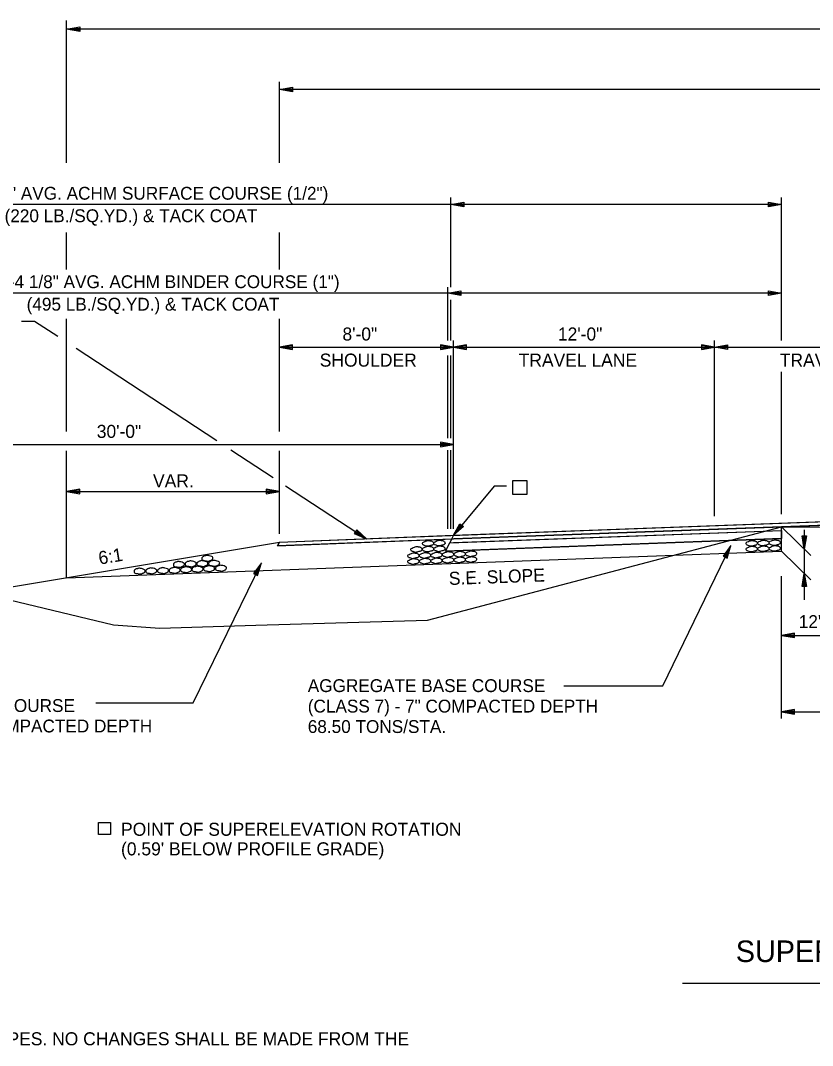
# Model space of a CAD drawing. Extents: x 1461846 to 1462006, y 1686171 to 1686805.
# Drawn here: x 1461877.78 to 1461914.18, y 1686329.7 to 1686376.8 of the extents above; entities that cross this region are included whole.
import ezdxf

# ---------------------------------------------------------------- set-up
doc = ezdxf.new("R2010")
doc.units = 0
for name, color, linetype in [('1', 7, 'Continuous'), ('10', 7, 'Continuous'), ('12', 7, 'Continuous'), ('19', 7, 'Continuous'), ('20', 7, 'Continuous'), ('3', 7, 'Continuous'), ('42', 7, 'Continuous'), ('R_Draft', 7, 'Continuous')]:
    doc.layers.add(name, color=color, linetype=linetype)

# ---------------------------------------------------------------- blocks, each defined once
blk = doc.blocks.new('ROCKS')
at = {"layer": '1'}
blk.add_spline([(0.013, 0.06), (0.053, 0.053), (0.107, 0.033), (0.133, 0.013), (0.133, -0.007), (0.12, -0.033), (0.107, -0.04), (0.073, -0.053), (0.033, -0.067), (0.013, -0.067), (-0.02, -0.06), (-0.06, -0.053), (-0.087, -0.047), (-0.113, -0.02), (-0.113, -0.007), (-0.107, 0.02), (-0.087, 0.033), (-0.067, 0.047), (-0.033, 0.053), (-0.02, 0.06), (0.013, 0.06)], degree=3, dxfattribs=at)

msp = doc.modelspace()

# ---------------------------------------------------------------- linework, layer by layer
at = {"layer": '10'}
msp.add_lwpolyline([(1461901.048, 1686355.021), (1461900.407, 1686355.021), (1461900.407, 1686355.662), (1461901.048, 1686355.662), (1461901.048, 1686355.021)], dxfattribs=at)
at = {"layer": '19'}
for p, q in [((1461912.763, 1686353.368), (1461912.763, 1686353.368)), ((1461897.68, 1686353.143), (1461897.318, 1686352.42)), ((1461913.703, 1686353.112), (1461913.913, 1686353.112)), ((1461913.808, 1686352.512), (1461913.703, 1686353.112)), ((1461913.793, 1686352.672), (1461913.753, 1686353.112)), ((1461913.913, 1686353.112), (1461913.808, 1686352.512)), ((1461913.858, 1686353.112), (1461913.823, 1686352.672)), ((1461889.68, 1686352.823), (1461889.595, 1686352.653)), ((1461897.318, 1686352.42), (1461897.51, 1686352.803)), ((1461897.51, 1686352.803), (1461897.51, 1686352.803)), ((1461907.301, 1686346.235), (1461910.435, 1686352.674)), ((1461910.435, 1686352.674), (1461910.071, 1686352.185)), ((1461910.353, 1686352.537), (1461910.12, 1686352.164)), ((1461910.214, 1686352.115), (1461910.378, 1686352.524)), ((1461910.258, 1686352.093), (1461910.435, 1686352.674)), ((1461897.318, 1686352.42), (1461897.318, 1686352.42)), ((1461910.071, 1686352.185), (1461910.258, 1686352.093)), ((1461885.72, 1686345.442), (1461888.854, 1686351.881)), ((1461888.854, 1686351.881), (1461888.49, 1686351.392)), ((1461888.772, 1686351.744), (1461888.539, 1686351.371)), ((1461888.633, 1686351.322), (1461888.797, 1686351.731)), ((1461888.677, 1686351.299), (1461888.854, 1686351.881)), ((1461888.49, 1686351.392), (1461888.677, 1686351.299)), ((1461913.703, 1686350.787), (1461913.808, 1686351.387)), ((1461913.758, 1686350.787), (1461913.793, 1686351.227)), ((1461913.808, 1686351.387), (1461913.913, 1686350.787)), ((1461913.823, 1686351.227), (1461913.863, 1686350.787)), ((1461913.913, 1686350.787), (1461913.703, 1686350.787)), ((1461902.757, 1686346.235), (1461907.301, 1686346.235)), ((1461881.246, 1686345.442), (1461885.72, 1686345.442))]:
    msp.add_line(p, q, dxfattribs=at)
for points in [[(1461964.762, 1686355.458), (1461960.956, 1686355.318), (1461940.777, 1686354.571), (1461921.639, 1686353.863), (1461914.019, 1686353.581), (1461903.26, 1686353.183), (1461897.595, 1686352.973), (1461895.595, 1686352.893), (1461889.595, 1686352.653), (1461889.595, 1686352.653), (1461889.595, 1686352.653), (1461889.68, 1686352.823), (1461889.68, 1686352.823), (1461889.68, 1686352.823), (1461895.545, 1686353.058), (1461903.665, 1686353.365), (1461913.994, 1686353.747), (1461921.643, 1686354.03), (1461940.732, 1686354.736), (1461960.903, 1686355.482), (1461964.68, 1686355.622)], [(1461897.51, 1686352.803), (1461897.68, 1686352.81), (1461912.763, 1686353.368), (1461912.763, 1686353.368), (1461912.763, 1686353.368), (1461912.763, 1686353.534), (1461912.763, 1686353.534), (1461912.763, 1686353.534), (1461897.7, 1686352.977), (1461897.595, 1686352.973)]]:
    msp.add_lwpolyline(points, close=True, dxfattribs=at)
for points in [[(1461912.763, 1686353.368), (1461912.763, 1686352.993), (1461897.318, 1686352.42), (1461897.318, 1686352.42), (1461897.318, 1686352.42)], [(1461897.51, 1686352.803), (1461897.51, 1686352.803), (1461897.51, 1686352.803), (1461912.763, 1686353.368)]]:
    msp.add_lwpolyline(points, dxfattribs=at)
at = {"layer": '20'}
for p, q in [((1461879.904, 1686370.26), (1461879.904, 1686376.797)), ((1461879.904, 1686376.393), (1461880.504, 1686376.499)), ((1461880.064, 1686376.408), (1461880.504, 1686376.444)), ((1461880.504, 1686376.499), (1461880.504, 1686376.289)), ((1461976.425, 1686376.393), (1461879.904, 1686376.393)), ((1461880.504, 1686376.289), (1461879.904, 1686376.393)), ((1461880.504, 1686376.339), (1461880.064, 1686376.378)), ((1461889.68, 1686370.26), (1461889.68, 1686373.976)), ((1461889.68, 1686373.624), (1461890.28, 1686373.729)), ((1461964.68, 1686373.624), (1461889.68, 1686373.624)), ((1461890.28, 1686373.519), (1461889.68, 1686373.624)), ((1461889.84, 1686373.639), (1461890.28, 1686373.674)), ((1461890.28, 1686373.729), (1461890.28, 1686373.519)), ((1461890.28, 1686373.569), (1461889.84, 1686373.609)), ((1461897.555, 1686364.538), (1461897.555, 1686368.657)), ((1461897.555, 1686368.339), (1461898.155, 1686368.444)), ((1461898.155, 1686368.444), (1461898.155, 1686368.234)), ((1461912.163, 1686368.234), (1461912.163, 1686368.444)), ((1461912.163, 1686368.444), (1461912.763, 1686368.339)), ((1461912.763, 1686362.092), (1461912.763, 1686368.657)), ((1461897.555, 1686368.339), (1461873.688, 1686368.339)), ((1461912.763, 1686368.339), (1461897.555, 1686368.339)), ((1461898.155, 1686368.234), (1461897.555, 1686368.339)), ((1461897.715, 1686368.354), (1461898.155, 1686368.389)), ((1461898.155, 1686368.284), (1461897.715, 1686368.324)), ((1461912.163, 1686368.389), (1461912.603, 1686368.354)), ((1461912.763, 1686368.339), (1461912.163, 1686368.234)), ((1461912.603, 1686368.324), (1461912.163, 1686368.284)), ((1461879.904, 1686365.357), (1461879.904, 1686367.061)), ((1461889.68, 1686365.357), (1461889.68, 1686367.061)), ((1461897.419, 1686364.27), (1461875.488, 1686364.27)), ((1461897.418, 1686364.27), (1461898.018, 1686364.375)), ((1461898.018, 1686364.165), (1461897.418, 1686364.27)), ((1461897.419, 1686362.092), (1461897.419, 1686364.538)), ((1461912.763, 1686364.272), (1461897.419, 1686364.272)), ((1461897.578, 1686364.285), (1461898.018, 1686364.32)), ((1461898.018, 1686364.215), (1461897.578, 1686364.255)), ((1461898.018, 1686364.375), (1461898.018, 1686364.165)), ((1461912.163, 1686364.167), (1461912.163, 1686364.377)), ((1461912.163, 1686364.377), (1461912.763, 1686364.272)), ((1461912.163, 1686364.322), (1461912.603, 1686364.287)), ((1461912.763, 1686364.272), (1461912.163, 1686364.167)), ((1461912.603, 1686364.257), (1461912.163, 1686364.217)), ((1461897.555, 1686362.092), (1461897.555, 1686363.96)), ((1461879.904, 1686357.918), (1461879.904, 1686363.084)), ((1461889.68, 1686362.092), (1461889.68, 1686363.084)), ((1461897.419, 1686357.605), (1461897.419, 1686361.398)), ((1461897.555, 1686357.605), (1461897.555, 1686361.398)), ((1461912.763, 1686354.12), (1461912.763, 1686360.658)), ((1461879.904, 1686351.194), (1461879.904, 1686357.018)), ((1461897.419, 1686353.443), (1461897.419, 1686357.062)), ((1461897.555, 1686353.443), (1461897.555, 1686357.062)), ((1461880.504, 1686355.266), (1461879.904, 1686355.161)), ((1461880.504, 1686355.056), (1461880.504, 1686355.266)), ((1461889.08, 1686355.266), (1461889.08, 1686355.056)), ((1461889.68, 1686355.161), (1461889.08, 1686355.266)), ((1461879.904, 1686355.161), (1461889.68, 1686355.161)), ((1461879.904, 1686355.161), (1461880.504, 1686355.056)), ((1461880.504, 1686355.211), (1461880.064, 1686355.176)), ((1461880.064, 1686355.146), (1461880.504, 1686355.106)), ((1461889.52, 1686355.176), (1461889.08, 1686355.211)), ((1461889.08, 1686355.056), (1461889.68, 1686355.161)), ((1461889.08, 1686355.106), (1461889.52, 1686355.146)), ((1461912.763, 1686353.534), (1461914.107, 1686352.219)), ((1461912.763, 1686352.409), (1461914.107, 1686351.094))]:
    msp.add_line(p, q, dxfattribs=at)
msp.add_lwpolyline([(1461913.808, 1686353.388), (1461913.808, 1686350.178)], dxfattribs=at)
at = {"layer": '3'}
msp.add_line((1461946.153, 1686332.55), (1461908.207, 1686332.55), dxfattribs=at)
at = {"layer": 'R_Draft'}
for p, q in [((1461889.68, 1686357.918), (1461889.68, 1686362.092)), ((1461890.28, 1686361.897), (1461889.68, 1686361.792)), ((1461890.28, 1686361.687), (1461890.28, 1686361.897)), ((1461897.08, 1686361.897), (1461897.08, 1686361.687)), ((1461897.68, 1686361.792), (1461897.08, 1686361.897)), ((1461897.68, 1686357.012), (1461897.68, 1686362.092)), ((1461898.28, 1686361.897), (1461897.68, 1686361.792)), ((1461898.28, 1686361.687), (1461898.28, 1686361.897)), ((1461909.08, 1686361.897), (1461909.08, 1686361.687)), ((1461909.68, 1686361.792), (1461909.08, 1686361.897)), ((1461909.68, 1686354.023), (1461909.68, 1686362.092)), ((1461909.68, 1686361.792), (1461910.28, 1686361.897)), ((1461910.28, 1686361.897), (1461910.28, 1686361.687)), ((1461889.68, 1686361.792), (1461897.68, 1686361.792)), ((1461889.68, 1686361.792), (1461890.28, 1686361.687)), ((1461890.28, 1686361.842), (1461889.84, 1686361.807)), ((1461889.84, 1686361.777), (1461890.28, 1686361.737)), ((1461897.52, 1686361.807), (1461897.08, 1686361.842)), ((1461897.08, 1686361.687), (1461897.68, 1686361.792)), ((1461897.08, 1686361.737), (1461897.52, 1686361.777)), ((1461897.68, 1686361.792), (1461909.68, 1686361.792)), ((1461897.68, 1686361.792), (1461898.28, 1686361.687)), ((1461898.28, 1686361.842), (1461897.84, 1686361.807)), ((1461897.84, 1686361.777), (1461898.28, 1686361.737)), ((1461909.52, 1686361.807), (1461909.08, 1686361.842)), ((1461909.08, 1686361.687), (1461909.68, 1686361.792)), ((1461909.08, 1686361.737), (1461909.52, 1686361.777)), ((1461909.68, 1686361.792), (1461921.68, 1686361.792)), ((1461910.28, 1686361.687), (1461909.68, 1686361.792)), ((1461909.84, 1686361.807), (1461910.28, 1686361.842)), ((1461910.28, 1686361.737), (1461909.84, 1686361.777)), ((1461867.68, 1686357.318), (1461897.68, 1686357.318)), ((1461897.08, 1686357.423), (1461897.08, 1686357.213)), ((1461897.68, 1686357.318), (1461897.08, 1686357.423)), ((1461897.52, 1686357.333), (1461897.08, 1686357.368)), ((1461897.08, 1686357.213), (1461897.68, 1686357.318)), ((1461897.08, 1686357.263), (1461897.52, 1686357.303)), ((1461889.68, 1686353.207), (1461889.68, 1686357.018)), ((1461897.68, 1686353.443), (1461897.68, 1686357.012)), ((1461893.236, 1686353.4), (1461893.121, 1686353.224)), ((1461893.68, 1686352.983), (1461893.236, 1686353.4)), ((1461897.68, 1686353.143), (1461897.978, 1686353.674)), ((1461898.139, 1686353.542), (1461897.68, 1686353.143)), ((1461897.772, 1686353.273), (1461898.016, 1686353.636)), ((1461898.102, 1686353.568), (1461897.793, 1686353.258)), ((1461897.978, 1686353.674), (1461898.139, 1686353.542)), ((1461912.763, 1686352.409), (1461912.763, 1686353.534)), ((1461889.595, 1686352.653), (1461897.68, 1686352.976)), ((1461889.68, 1686352.823), (1461897.68, 1686353.143)), ((1461893.121, 1686353.224), (1461893.68, 1686352.983)), ((1461893.151, 1686353.27), (1461893.538, 1686353.058)), ((1461893.554, 1686353.083), (1461893.208, 1686353.358)), ((1461867.68, 1686349.156), (1461889.68, 1686352.823)), ((1461897.318, 1686352.42), (1461897.68, 1686352.435)), ((1461897.51, 1686352.803), (1461897.68, 1686352.81)), ((1461912.763, 1686344.731), (1461912.763, 1686351.268)), ((1461913.358, 1686348.652), (1461912.758, 1686348.547)), ((1461912.758, 1686348.547), (1461924.763, 1686348.547)), ((1461912.758, 1686348.547), (1461913.358, 1686348.442)), ((1461913.358, 1686348.597), (1461912.918, 1686348.562)), ((1461912.918, 1686348.532), (1461913.358, 1686348.492)), ((1461913.358, 1686348.442), (1461913.358, 1686348.652)), ((1461913.363, 1686345.138), (1461912.763, 1686345.033)), ((1461912.763, 1686345.033), (1461940.18, 1686345.033)), ((1461912.763, 1686345.033), (1461913.363, 1686344.928)), ((1461913.363, 1686345.083), (1461912.923, 1686345.048)), ((1461912.923, 1686345.018), (1461913.363, 1686344.978)), ((1461913.363, 1686344.928), (1461913.363, 1686345.138))]:
    msp.add_line(p, q, dxfattribs=at)
for points in [[(1461877.833, 1686362.988), (1461878.433, 1686362.988), (1461879.498, 1686362.289)], [(1461880.338, 1686361.737), (1461886.801, 1686357.497)], [(1461887.444, 1686357.075), (1461889.4, 1686355.792)], [(1461889.967, 1686355.419), (1461893.68, 1686352.983)], [(1461900.123, 1686355.407), (1461899.553, 1686355.407), (1461897.68, 1686353.143)], [(1461897.68, 1686353.143), (1461927.18, 1686354.235), (1461956.68, 1686355.326)], [(1461900.407, 1686355.021), (1461900.407, 1686355.662), (1461901.048, 1686355.662), (1461901.048, 1686355.021), (1461900.407, 1686355.021)], [(1461897.68, 1686352.976), (1461927.18, 1686354.068), (1461956.68, 1686355.159)], [(1461847.362, 1686353.269), (1461867.322, 1686352.565), (1461882.06, 1686349.033), (1461884.194, 1686348.879), (1461888.604, 1686349.011), (1461896.486, 1686349.242), (1461912.763, 1686353.534), (1461918.661, 1686353.486), (1461934.122, 1686354.079), (1461940.18, 1686354.549), (1461946.68, 1686353.887), (1461962.552, 1686349.481)], [(1461897.68, 1686352.976), (1461918.68, 1686353.753)], [(1461897.68, 1686352.81), (1461912.763, 1686353.368)], [(1461897.68, 1686352.435), (1461912.763, 1686352.993)], [(1461879.904, 1686351.194), (1461912.763, 1686352.409)], [(1461881.362, 1686339.396), (1461881.362, 1686339.956), (1461881.922, 1686339.956), (1461881.922, 1686339.396), (1461881.362, 1686339.396)]]:
    msp.add_lwpolyline(points, dxfattribs=at)

# ---------------------------------------------------------------- block references
at = {"layer": '19'}
for p, xscale, yscale, rotation in [((1461896.532, 1686352.781), 2.0611362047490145, -2.0611362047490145, -176.23624371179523), ((1461897.06, 1686352.796), 2.0611362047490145, -2.0611362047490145, -176.23624371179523), ((1461911.412, 1686352.783), 2.0611362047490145, -2.0611362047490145, -176.23624371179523), ((1461911.942, 1686352.799), 2.0611362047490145, -2.0611362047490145, -176.23624371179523), ((1461912.47, 1686352.814), 2.0611362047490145, -2.0611362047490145, -176.23624371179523), ((1461896.002, 1686352.503), 2.0611362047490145, -2.0611362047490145, -176.23624371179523), ((1461896.532, 1686352.519), 2.0611362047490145, -2.0611362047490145, -176.23624371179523), ((1461897.06, 1686352.534), 2.0611362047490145, -2.0611362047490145, -176.23624371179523), ((1461897.985, 1686352.286), 2.0611362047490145, -2.0611362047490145, -176.23624371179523), ((1461898.514, 1686352.302), 2.0611362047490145, -2.0611362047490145, -176.23624371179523), ((1461911.412, 1686352.521), 2.0611362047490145, -2.0611362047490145, -176.23624371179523), ((1461911.942, 1686352.537), 2.0611362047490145, -2.0611362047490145, -176.23624371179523), ((1461912.471, 1686352.552), 2.0611362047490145, -2.0611362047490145, -176.23624371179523), ((1461885.587, 1686351.839), 2.061136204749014, 2.061136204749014, 1.3628294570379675), ((1461886.121, 1686351.851), 2.061136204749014, 2.061136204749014, 1.3628294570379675), ((1461886.352, 1686352.095), 2.061136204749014, 2.061136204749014, 1.3628294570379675), ((1461886.663, 1686351.864), 2.061136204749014, 2.061136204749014, 1.3628294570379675), ((1461895.864, 1686352.211), 2.0611362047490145, -2.0611362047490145, -176.23624371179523), ((1461895.864, 1686351.949), 2.0611362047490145, -2.0611362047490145, -176.23624371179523), ((1461896.393, 1686352.227), 2.0611362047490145, -2.0611362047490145, -176.23624371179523), ((1461896.393, 1686351.965), 2.0611362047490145, -2.0611362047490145, -176.23624371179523), ((1461896.922, 1686352.243), 2.0611362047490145, -2.0611362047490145, -176.23624371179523), ((1461896.922, 1686351.981), 2.0611362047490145, -2.0611362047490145, -176.23624371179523), ((1461897.456, 1686352.271), 2.0611362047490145, -2.0611362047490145, -176.23624371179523), ((1461897.456, 1686352.009), 2.0611362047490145, -2.0611362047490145, -176.23624371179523), ((1461897.986, 1686352.024), 2.0611362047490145, -2.0611362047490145, -176.23624371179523), ((1461898.514, 1686352.04), 2.0611362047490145, -2.0611362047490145, -176.23624371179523), ((1461883.235, 1686351.503), 2.061136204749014, 2.061136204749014, 1.3628294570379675), ((1461883.774, 1686351.516), 2.061136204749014, 2.061136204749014, 1.3628294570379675), ((1461884.317, 1686351.529), 2.061136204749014, 2.061136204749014, 1.3628294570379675), ((1461884.844, 1686351.541), 2.061136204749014, 2.061136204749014, 1.3628294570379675), ((1461885.045, 1686351.81), 2.061136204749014, 2.061136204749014, 1.3628294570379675), ((1461885.375, 1686351.569), 2.061136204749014, 2.061136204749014, 1.3628294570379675), ((1461885.898, 1686351.594), 2.061136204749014, 2.061136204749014, 1.3628294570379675), ((1461886.431, 1686351.617), 2.061136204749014, 2.061136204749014, 1.3628294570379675), ((1461886.976, 1686351.639), 2.061136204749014, 2.061136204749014, 1.3628294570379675)]:
    msp.add_blockref('ROCKS', p, dxfattribs=dict(at, xscale=xscale, yscale=yscale, rotation=rotation))

# ---------------------------------------------------------------- texts
at = {"layer": '12'}
msp.add_text('SUPERELEVATED NOTCH AND WIDEN SECTION', height=0.98999, rotation=0.0046, dxfattribs=at).set_placement((1461910.658, 1686333.537))
at = {"layer": '19'}
for s, p in [('AGGREGATE BASE COURSE', (1461890.987, 1686345.941)), ('AGGREGATE BASE COURSE', (1461869.369, 1686345.026)), ('(CLASS 7) - 7" COMPACTED DEPTH', (1461890.987, 1686345.001)), ('(CLASS 7) - VAR. COMPACTED DEPTH', (1461869.369, 1686344.086)), ('68.50 TONS/STA.', (1461890.987, 1686344.061))]:
    msp.add_text(s, height=0.59001, dxfattribs=at).set_placement(p)
at = {"layer": '42'}
for s, p in [('15\'-2 1/2" AVG. ACHM SURFACE COURSE (1/2")', (1461874.254, 1686368.564)), ('(220 LB./SQ.YD.) & TACK COAT', (1461877.053, 1686367.531)), ('15\'-4 1/8" AVG. ACHM BINDER COURSE (1")', (1461876.219, 1686364.5)), ('(495 LB./SQ.YD.) & TACK COAT', (1461878.066, 1686363.467)), ("12' EXISTING PAVEMENT", (1461913.555, 1686348.885))]:
    msp.add_text(s, height=0.59001, dxfattribs=at).set_placement(p)
at = {"layer": 'R_Draft'}
for s, p in [('8\'-0"', (1461892.581, 1686362.092)), ('12\'-0"', (1461902.482, 1686362.092)), ('SHOULDER', (1461891.537, 1686360.892)), ('TRAVEL LANE', (1461900.68, 1686360.892)), ('TRAVEL LANE', (1461912.68, 1686360.892)), ('30\'-0"', (1461881.289, 1686357.618)), ('REFER TO CROSS SECTIONS FOR DEVIATIONS FROM NORMAL SLOPES. NO CHANGES SHALL BE MADE FROM THE ', (1461850.662, 1686329.711))]:
    msp.add_text(s, height=0.6, dxfattribs=at).set_placement(p)
for s, rotation, p in [('VAR.', 360, (1461883.875, 1686355.344)), ('6:1', 9.4825, (1461881.419, 1686351.795)), ('S.E. SLOPE', 2.119, (1461897.481, 1686350.86)), ('POINT OF SUPERELEVATION ROTATION', 0.0046, (1461882.404, 1686339.337)), ("(0.59' BELOW PROFILE GRADE)", 0.0046, (1461882.404, 1686338.437))]:
    msp.add_text(s, height=0.6, rotation=rotation, dxfattribs=at).set_placement(p)

doc.saveas('drawing.dxf')
